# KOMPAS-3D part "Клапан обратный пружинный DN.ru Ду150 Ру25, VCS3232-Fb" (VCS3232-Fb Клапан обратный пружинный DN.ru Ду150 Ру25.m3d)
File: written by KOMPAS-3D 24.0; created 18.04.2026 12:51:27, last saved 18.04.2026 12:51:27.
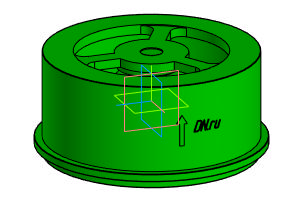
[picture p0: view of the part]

Document properties: Автор: 712; Полное имя файла: C:\Users\712\Desktop\Новая папка (4)\VCS3232-Fb Клапан обратный пружинный DN.ru Ду150 Ру25.m3d

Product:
- Component: Пружина 1086-1091 ГОСТ 18793-80  | qty 1  | additional columns: 3953604318-4147491677-0; Деталь; Пользователь Windows; c; Шероховатость не задана; Да; Сталь 10  ГОСТ 1050-88; source file: Деталь_2.m3d
- Body: Тело 1  | qty 1
    Масса: 8.55169
- Part/product: Клапан обратный пружинный DN.ru Ду150 Ру25  | designation VCS3232-Fb
    Масса: 5.7
    Раздел спецификации: Прочие изделия
    Примечание: D100-03907
    additional columns: 071bd168-1a06-425c-849c-e99e84a96128; Деталь; 712; c; Шероховатость не задана; Да

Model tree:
1. Операция без истории:2

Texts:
  VCS3232-Fb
